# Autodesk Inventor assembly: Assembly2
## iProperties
Shininess: 64.0
Length Units: 11269
Angle Units: 11279
Time Units: 11290
Mass Units: 11283
Length Display Precision: 3
Angle Display Precision: 2
Compacted: True
Created: 2003-01
Part Number: Assembly2
Document SubType Name: Weldment
Designer: Owner
Density: 0.0
Volumn: 0.0
Area: 0.0
PropertySet Name: Model Information
Control State: 0
Master: False
Checked Out: False
Author: Owner
